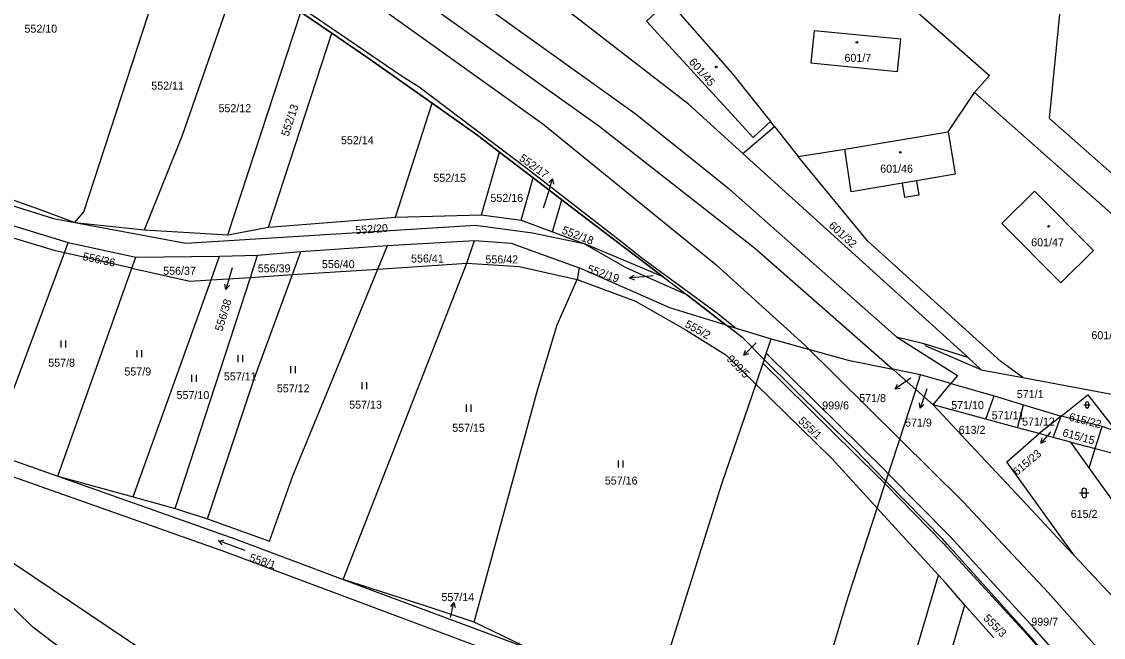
# Model space of a CAD drawing. Extents: x -757266 to -753360, y -1162585 to -1157740.
# Drawn here: x -756391.6 to -756161.8, y -1161170.8 to -1161040 of the extents above; entities that cross this region are included whole.
import ezdxf

# ---------------------------------------------------------------- set-up
doc = ezdxf.new("R2010")
doc.units = 0
for name, color, linetype in [('Hranice parcel', 7, 'Continuous'), ('Parcelní čísla', 7, 'Continuous'), ('Pop  PČ popisy', 7, 'Continuous'), ('Poz předměty', 7, 'Continuous'), ('Vnitřní kresba', 7, 'Continuous'), ('Věcná břemena k části', 7, 'Continuous'), ('Značky budov', 7, 'Continuous'), ('Značky kultur', 7, 'Continuous')]:
    doc.layers.add(name, color=color, linetype=linetype)

msp = doc.modelspace()

# ---------------------------------------------------------------- linework, layer by layer
at = {"layer": 'Hranice parcel'}
for p, q in [((-756347.81, -1161085.34), (-756332.31, -1161038.03)), ((-756325.74, -1161042.49), (-756332.31, -1161038.03)), ((-756339.16, -1161083.67), (-756325.74, -1161042.49)), ((-756194.79, -1161063.47), (-756189.22, -1161055.1)), ((-756189.22, -1161055.1), (-756130.57, -1161106.95)), ((-756312.16, -1161081.58), (-756304.38, -1161057.38)), ((-756238.39, -1161068.03), (-756231.69, -1161062.33)), ((-756231.69, -1161062.33), (-756232.53, -1161061.27)), ((-756231.69, -1161062.33), (-756226.63, -1161068.72)), ((-756216.76, -1161067.14), (-756194.79, -1161063.47)), ((-756226.63, -1161068.72), (-756216.76, -1161067.14)), ((-756293.95, -1161081.1), (-756290.12, -1161067.73)), ((-756282.98, -1161073.2), (-756290.12, -1161067.73)), ((-756190.6, -1161111.29), (-756238.39, -1161068.03)), ((-756285.46, -1161082.24), (-756282.98, -1161073.2)), ((-756276.88, -1161077.87), (-756282.98, -1161073.2)), ((-756278.82, -1161084.68), (-756276.88, -1161077.87)), ((-756402.04, -1161080.71), (-756381.71, -1161086.97)), ((-756312.16, -1161081.58), (-756293.95, -1161081.1)), ((-756293.95, -1161081.1), (-756285.46, -1161082.24)), ((-756380.33, -1161082.7), (-756365.53, -1161084.29)), ((-756347.81, -1161085.34), (-756339.16, -1161083.67)), ((-756339.16, -1161083.67), (-756312.16, -1161081.58)), ((-756285.46, -1161082.24), (-756278.82, -1161084.68)), ((-756365.53, -1161084.29), (-756347.81, -1161085.34)), ((-756278.82, -1161084.68), (-756272.16, -1161087.13)), ((-756382.52, -1161089.15), (-756381.71, -1161086.97)), ((-756381.71, -1161086.97), (-756367.38, -1161090.04)), ((-756332.27, -1161088.89), (-756313.86, -1161087.61)), ((-756315.91, -1161092.58), (-756313.86, -1161087.61)), ((-756313.86, -1161087.61), (-756295.39, -1161086.52)), ((-756297.07, -1161091.35), (-756295.39, -1161086.52)), ((-756255.3, -1161094.26), (-756272.16, -1161087.13)), ((-756398.32, -1161131.47), (-756382.52, -1161089.15)), ((-756368.21, -1161092.38), (-756382.52, -1161089.15)), ((-756368.21, -1161092.38), (-756367.38, -1161090.04)), ((-756367.38, -1161090.04), (-756349.55, -1161089.83)), ((-756351.37, -1161094.89), (-756349.55, -1161089.83)), ((-756349.55, -1161089.83), (-756341.48, -1161089.62)), ((-756343.02, -1161094.35), (-756341.48, -1161089.62)), ((-756341.48, -1161089.62), (-756332.27, -1161088.89)), ((-756334.06, -1161093.76), (-756332.27, -1161088.89)), ((-756383.91, -1161136.58), (-756368.21, -1161092.38)), ((-756334.06, -1161093.76), (-756315.91, -1161092.58)), ((-756323.3, -1161158.51), (-756297.07, -1161091.35)), ((-756315.91, -1161092.58), (-756297.07, -1161091.35)), ((-756273.15, -1161092.35), (-756273.61, -1161094.81)), ((-756367.91, -1161140.96), (-756351.37, -1161094.89)), ((-756359.01, -1161143.46), (-756343.02, -1161094.35)), ((-756351.37, -1161094.89), (-756343.02, -1161094.35)), ((-756343.02, -1161094.35), (-756334.06, -1161093.76)), ((-756255.3, -1161094.26), (-756250.36, -1161098)), ((-756241.96, -1161104.51), (-756250.36, -1161098)), ((-756241.96, -1161104.51), (-756232.4, -1161107.44)), ((-756233.87, -1161111.77), (-756232.4, -1161107.44)), ((-756233.87, -1161111.77), (-756235.67, -1161117.05)), ((-756206.58, -1161113.87), (-756201.69, -1161118.16)), ((-756200.68, -1161115.05), (-756206.58, -1161113.87)), ((-756201.69, -1161118.16), (-756200.68, -1161115.05)), ((-756194.25, -1161116.88), (-756200.68, -1161115.05)), ((-756201.69, -1161118.16), (-756208.01, -1161137.65)), ((-756197.99, -1161121.41), (-756201.69, -1161118.16)), ((-756197.99, -1161121.41), (-756194.25, -1161116.88)), ((-756194.25, -1161116.88), (-756185.01, -1161119.51)), ((-756186.8, -1161124.46), (-756185.01, -1161119.51)), ((-756185.01, -1161119.51), (-756178.8, -1161121.43)), ((-756186.8, -1161124.46), (-756197.99, -1161121.41)), ((-756180.08, -1161126.29), (-756178.8, -1161121.43)), ((-756178.8, -1161121.43), (-756170.8, -1161123.82)), ((-756180.08, -1161126.29), (-756186.8, -1161124.46)), ((-756170.8, -1161123.82), (-756175.48, -1161127.54)), ((-756172.5, -1161128.35), (-756170.8, -1161123.82)), ((-756162.05, -1161126.01), (-756170.8, -1161123.82)), ((-756175.48, -1161127.54), (-756180.08, -1161126.29)), ((-756159.03, -1161127.11), (-756162.05, -1161126.01)), ((-756172.5, -1161128.35), (-756175.48, -1161127.54)), ((-756398.32, -1161131.47), (-756383.91, -1161136.58)), ((-756153.73, -1161150.3), (-756164.84, -1161134.81)), ((-756383.91, -1161136.58), (-756367.91, -1161140.96)), ((-756209.87, -1161143.4), (-756208.01, -1161137.65)), ((-756367.91, -1161140.96), (-756359.01, -1161143.46)), ((-756209.87, -1161143.4), (-756196.87, -1161157.63)), ((-756359.01, -1161143.46), (-756352.09, -1161145.66)), ((-756167.94, -1161153.53), (-756157.64, -1161164.54)), ((-756323.3, -1161158.51), (-756283.74, -1161173.27)), ((-756185.1, -1161170.94), (-756191.26, -1161163.95)), ((-756283.74, -1161173.27), (-756295.45, -1161167.59))]:
    msp.add_line(p, q, dxfattribs=at)
for points in [[(-756619.33, -1160903.88), (-756577.49, -1160910.26), (-756516.69, -1160926.33), (-756477.86, -1160938.97), (-756467.28, -1160942.69), (-756436.37, -1160956.11), (-756402.66, -1160971.04), (-756365.31, -1160990.59), (-756332.18, -1161010.49), (-756327.59, -1161013.25), (-756311.79, -1161023.35), (-756261.25, -1161059.52), (-756244.95, -1161072.68), (-756241.63, -1161075.37), (-756205.74, -1161107.01)], [(-756619.9, -1160909.59), (-756570.69, -1160918.36), (-756518.23, -1160931.61), (-756479.8, -1160944.32), (-756438.52, -1160960.99), (-756404.97, -1160975.81), (-756367.56, -1160995.11), (-756330.79, -1161017.74), (-756301.4, -1161039.07), (-756269.03, -1161062.15), (-756235.9, -1161088.11), (-756216.97, -1161104.74), (-756206.58, -1161113.87)], [(-756108.4, -1161121.99), (-756143.44, -1161091.07), (-756148.04, -1161082.81), (-756173.25, -1161060.58), (-756158.32, -1160909.77)], [(-756284.06, -1160946.51), (-756265.23, -1160959.87), (-756261.78, -1160964.32), (-756259.59, -1160972.58), (-756254.14, -1160987.97), (-756251.24, -1160993.15), (-756247.24, -1160997.7), (-756201.76, -1161037.66), (-756186.03, -1161051.48), (-756189.22, -1161055.1)], [(-756238.39, -1161068.03), (-756249.95, -1161057.57), (-756286.42, -1161029.31), (-756325.51, -1161006.88), (-756320.49, -1160993.89), (-756312.28, -1160987.12), (-756309.4, -1160983.82)], [(-756380.33, -1161082.7), (-756378.4, -1161080.44), (-756358.96, -1161020.98)], [(-756365.53, -1161084.29), (-756357.4, -1161064.17), (-756345.3, -1161029.34)], [(-756232.53, -1161061.27), (-756236.18, -1161064.68), (-756258.84, -1161039.93), (-756254.18, -1161035.65)], [(-756254.18, -1161035.65), (-756240.57, -1161051.12), (-756232.53, -1161061.27)], [(-756204.82, -1161043.76), (-756223.27, -1161041.98), (-756223.94, -1161048.76), (-756205.52, -1161050.62), (-756204.82, -1161043.76)], [(-756304.38, -1161057.38), (-756318.26, -1161047.57), (-756325.74, -1161042.49)], [(-756503.07, -1161050.14), (-756482.76, -1161051.05), (-756384.84, -1161081.86), (-756380.33, -1161082.7)], [(-756290.12, -1161067.73), (-756294.69, -1161064.23), (-756304.38, -1161057.38)], [(-756194.79, -1161063.47), (-756193.29, -1161072.46), (-756201.55, -1161073.85), (-756201.05, -1161076.93), (-756203.99, -1161077.39), (-756204.5, -1161074.36), (-756215.42, -1161076.19), (-756216.76, -1161067.14)], [(-756417.55, -1161069.42), (-756387.87, -1161079.86), (-756380.33, -1161082.7)], [(-756178.9, -1161115.62), (-756183.59, -1161112.25), (-756211.93, -1161086.58), (-756226.63, -1161068.72)], [(-756170.89, -1161095.55), (-756183.39, -1161082.92), (-756176.42, -1161076.03), (-756163.94, -1161088.68), (-756170.89, -1161095.55)], [(-756255.3, -1161094.26), (-756269.72, -1161083.35), (-756276.88, -1161077.87)], [(-756382.52, -1161089.15), (-756384.41, -1161088.72), (-756403, -1161083.12)], [(-756380.33, -1161082.7), (-756356.72, -1161087.11), (-756295.17, -1161083.25), (-756283.1, -1161084.88), (-756272.16, -1161087.13)], [(-756295.39, -1161086.52), (-756287.63, -1161087.12), (-756273.15, -1161092.35)], [(-756272.16, -1161087.13), (-756263.25, -1161092.24), (-756250.36, -1161098)], [(-756368.21, -1161092.38), (-756355.85, -1161095.18), (-756351.37, -1161094.89)], [(-756352.09, -1161145.66), (-756338.96, -1161150.42), (-756334.03, -1161136.54), (-756315.91, -1161092.58)], [(-756297.07, -1161091.35), (-756285.9, -1161092.02), (-756273.61, -1161094.81)], [(-756241.96, -1161104.51), (-756253.93, -1161100.85), (-756273.15, -1161092.35)], [(-756352.09, -1161145.66), (-756342.18, -1161115.92), (-756334.06, -1161093.76)], [(-756295.45, -1161167.59), (-756282.01, -1161118.28), (-756277.83, -1161104.44), (-756273.61, -1161094.81)], [(-756273.61, -1161094.81), (-756261.22, -1161099.39), (-756250.3, -1161105.63), (-756242.04, -1161110.83), (-756235.67, -1161117.05)], [(-756233.87, -1161111.77), (-756238.37, -1161107.3), (-756241.96, -1161104.51)], [(-756232.4, -1161107.44), (-756216.05, -1161111.97), (-756206.58, -1161113.87)], [(-756205.74, -1161107.01), (-756199.98, -1161108.4), (-756190.6, -1161111.29)], [(-756205.74, -1161107.01), (-756192.84, -1161115.17), (-756194.25, -1161116.88)], [(-756208.01, -1161137.65), (-756214.86, -1161130.65), (-756233.87, -1161111.77)], [(-756190.6, -1161111.29), (-756187.81, -1161113.97), (-756178.9, -1161115.62)], [(-756178.9, -1161115.62), (-756140.04, -1161122.9), (-756113.43, -1161127.66)], [(-756235.67, -1161117.05), (-756242.91, -1161138.3), (-756255.92, -1161179.51), (-756258.81, -1161182.58)], [(-756235.67, -1161117.05), (-756219.53, -1161132.83), (-756209.87, -1161143.4)], [(-756170.8, -1161123.82), (-756165.1, -1161119.29), (-756159.03, -1161127.11)], [(-756289.81, -1161247.85), (-756323.85, -1161218.81), (-756352.34, -1161196.76), (-756389.25, -1161168.62), (-756413.98, -1161144.42), (-756440.09, -1161120.71)], [(-756437.21, -1161121.24), (-756348.29, -1161152.64), (-756260.39, -1161185.58)], [(-756277.8, -1161225.59), (-756364.81, -1161174.31), (-756397.31, -1161152.49), (-756437.21, -1161121.24)], [(-756197.99, -1161121.41), (-756188.99, -1161131.03), (-756183.37, -1161137.03), (-756177.1, -1161143.73), (-756169.72, -1161151.63), (-756167.94, -1161153.53)], [(-756164.84, -1161134.81), (-756163.54, -1161130.72), (-756162.05, -1161126.01)], [(-756167.94, -1161153.53), (-756182.35, -1161133.54), (-756175.48, -1161127.54)], [(-756164.84, -1161134.81), (-756168.73, -1161129.38), (-756172.5, -1161128.35)], [(-756383.91, -1161136.58), (-756346.14, -1161149.99), (-756323.3, -1161158.51)], [(-756157.07, -1161193.58), (-756163.59, -1161186.21), (-756175.51, -1161172.74), (-756177.18, -1161170.86), (-756183.13, -1161164.23), (-756189.32, -1161157.34), (-756194.93, -1161151.09), (-756195.96, -1161149.95), (-756208.01, -1161137.65)], [(-756248.25, -1161269.62), (-756215.93, -1161162.08), (-756209.87, -1161143.4)], [(-756295.45, -1161167.59), (-756305.43, -1161164.28), (-756323.3, -1161158.51)], [(-756231.49, -1161276.35), (-756202.05, -1161175.12), (-756196.87, -1161157.63)], [(-756191.26, -1161163.95), (-756195.25, -1161159.41), (-756196.87, -1161157.63)], [(-756224.06, -1161280.46), (-756199.31, -1161191.43), (-756191.26, -1161163.95)]]:
    msp.add_lwpolyline(points, dxfattribs=at)
at = {"layer": 'Pop  PČ popisy'}
for p, q in [((-756279.72, -1161076.3), (-756278.843, -1161073.43)), ((-756278.843, -1161073.43), (-756279.614, -1161074.241)), ((-756278.843, -1161073.43), (-756278.657, -1161074.534)), ((-756280.73, -1161079.56), (-756279.72, -1161076.3)), ((-756346.91, -1161092.33), (-756347.41, -1161094.04)), ((-756347.41, -1161094.04), (-756348.237, -1161096.925)), ((-756262.45, -1161094.472), (-756261.496, -1161093.885)), ((-756259.46, -1161094.21), (-756262.45, -1161094.472)), ((-756262.45, -1161094.472), (-756261.408, -1161094.883)), ((-756257.45, -1161094.02), (-756259.46, -1161094.21)), ((-756348.237, -1161096.925), (-756348.442, -1161095.824)), ((-756348.237, -1161096.925), (-756347.48, -1161096.1)), ((-756236.06, -1161108.76), (-756238.182, -1161110.882)), ((-756235.56, -1161108.26), (-756236.06, -1161108.76)), ((-756238.182, -1161110.882), (-756237.828, -1161109.82)), ((-756238.182, -1161110.882), (-756237.12, -1161110.528)), ((-756202.7, -1161115.74), (-756203.59, -1161116.34)), ((-756203.59, -1161116.34), (-756206.078, -1161118.018)), ((-756206.078, -1161118.018), (-756205.528, -1161117.043)), ((-756206.078, -1161118.018), (-756204.968, -1161117.873)), ((-756199.35, -1161118.06), (-756199.76, -1161119.28)), ((-756199.76, -1161119.28), (-756200.737, -1161122.117)), ((-756200.737, -1161122.117), (-756200.884, -1161121.008)), ((-756200.737, -1161122.117), (-756199.938, -1161121.334)), ((-756173.13, -1161127.29), (-756175.099, -1161129.555)), ((-756173.03, -1161127.18), (-756173.13, -1161127.29)), ((-756175.099, -1161129.555), (-756174.82, -1161128.471)), ((-756175.099, -1161129.555), (-756174.064, -1161129.128)), ((-756299.775, -1161163.416), (-756300.488, -1161164.279)), ((-756300.45, -1161166.34), (-756299.775, -1161163.416)), ((-756299.775, -1161163.416), (-756299.512, -1161164.504)), ((-756300.5, -1161166.58), (-756300.45, -1161166.34))]:
    msp.add_line(p, q, dxfattribs=at)
at = {"layer": 'Poz předměty'}
for p, q in [((-756318.84, -1161034.56), (-756280.92, -1161061.74)), ((-756280.92, -1161061.74), (-756244.17, -1161091.62)), ((-756244.17, -1161091.62), (-756225.27, -1161108.74)), ((-756225.27, -1161108.74), (-756191.67, -1161141.97)), ((-756191.67, -1161141.97), (-756173.56, -1161161.31)), ((-756173.56, -1161161.31), (-756155.48, -1161181.52))]:
    msp.add_line(p, q, dxfattribs=at)
at = {"layer": 'Vnitřní kresba'}
for p, q in [((-756201.55, -1161073.85), (-756204.5, -1161074.36)), ((-756199.98, -1161108.4), (-756199.34, -1161109.03)), ((-756187.81, -1161113.97), (-756199.34, -1161109.03)), ((-756168.73, -1161129.38), (-756163.54, -1161130.72)), ((-756163.54, -1161130.72), (-756154.4, -1161133.07))]:
    msp.add_line(p, q, dxfattribs=at)
at = {"layer": 'Věcná břemena k části'}
for points in [[(-756332.31, -1161038.03), (-756325.74, -1161042.49), (-756318.26, -1161047.57), (-756304.38, -1161057.38), (-756294.69, -1161064.23), (-756290.12, -1161067.73), (-756282.98, -1161073.2), (-756276.88, -1161077.87), (-756269.72, -1161083.35), (-756255.3, -1161094.26), (-756250.36, -1161098), (-756241.96, -1161104.51), (-756240.03, -1161105.1), (-756243.69, -1161102.08), (-756259.84, -1161090.3), (-756260.26, -1161089.95), (-756264.06, -1161086.97), (-756283.95, -1161071.51), (-756307.16, -1161053.98), (-756310.78, -1161051.69), (-756335.39, -1161034.83)], [(-756149.8, -1161200.9), (-756162.23, -1161185.13), (-756176.59, -1161168.81), (-756194.29, -1161149.48), (-756207.51, -1161136.1), (-756208.28, -1161135.32), (-756233, -1161110.9), (-756233.45, -1161110.53), (-756233.87, -1161111.77), (-756234.15, -1161112.58), (-756209.69, -1161136.73), (-756208.2, -1161138.24), (-756195.75, -1161150.85), (-756178.05, -1161170.17), (-756163.77, -1161186.41), (-756157.34, -1161194.55)]]:
    msp.add_lwpolyline(points, dxfattribs=at)
at = {"layer": 'Značky budov'}
for centre in [(-756214.1768, -1161044.4492), (-756244.0768, -1161049.6892), (-756204.9568, -1161067.7992), (-756173.4468, -1161083.5292)]:
    msp.add_circle(centre, 0.175, dxfattribs=at)
at = {"layer": 'Značky kultur'}
for p, q in [((-756383.231, -1161109.24), (-756383.231, -1161107.74)), ((-756382.23, -1161109.24), (-756382.23, -1161107.74)), ((-756367.061, -1161111.32), (-756367.061, -1161109.82)), ((-756366.06, -1161111.32), (-756366.06, -1161109.82)), ((-756345.611, -1161112.37), (-756345.611, -1161110.87)), ((-756344.61, -1161112.37), (-756344.61, -1161110.87)), ((-756334.451, -1161114.72), (-756334.451, -1161113.22)), ((-756333.45, -1161114.72), (-756333.45, -1161113.22)), ((-756355.451, -1161116.54), (-756355.451, -1161115.04)), ((-756354.45, -1161116.54), (-756354.45, -1161115.04)), ((-756319.251, -1161118.1), (-756319.251, -1161116.6)), ((-756318.25, -1161118.1), (-756318.25, -1161116.6)), ((-756297.111, -1161122.89), (-756297.111, -1161121.39)), ((-756296.11, -1161122.89), (-756296.11, -1161121.39)), ((-756165.951, -1161121.451), (-756164.609, -1161121.451)), ((-756165.615, -1161121.115), (-756165.615, -1161121.786)), ((-756164.945, -1161121.786), (-756164.945, -1161121.115)), ((-756264.821, -1161134.72), (-756264.821, -1161133.22)), ((-756263.82, -1161134.72), (-756263.82, -1161133.22)), ((-756166.891, -1161140.131), (-756164.889, -1161140.131)), ((-756166.391, -1161139.631), (-756166.391, -1161140.632)), ((-756165.389, -1161140.632), (-756165.389, -1161139.631)), ((-756349.762, -1161150.34), (-756348.673, -1161150.203)), ((-756344.124, -1161152.392), (-756349.762, -1161150.34)), ((-756349.762, -1161150.34), (-756349.016, -1161151.145))]:
    msp.add_line(p, q, dxfattribs=at)
for centre, radius, start, end in [((-756165.28, -1161121.1156), 0.335, 0, 180), ((-756165.28, -1161121.7856), 0.335, 180, 359.987886), ((-756165.89, -1161139.6309), 0.5, 0, 180), ((-756165.89, -1161140.6309), 0.5, 180, 359.987886)]:
    msp.add_arc(centre, radius, start, end, dxfattribs=at)

# ---------------------------------------------------------------- texts
at = {"layer": 'Parcelní čísla'}
for s, p in [('552/10', (-756391.01, -1161042.39)), ('601/7', (-756216.82, -1161048.58)), ('552/11', (-756364.07, -1161054.49)), ('552/12', (-756349.79, -1161059.28)), ('552/14', (-756323.78, -1161066.07)), ('601/46', (-756209.227, -1161072.11)), ('552/15', (-756304.16, -1161074.06)), ('552/16', (-756292.03, -1161078.33)), ('601/47', (-756177.157, -1161087.76)), ('556/41', (-756308.89, -1161091.2)), ('556/42', (-756293.09, -1161091.39)), ('556/37', (-756361.54, -1161093.81)), ('556/39', (-756341.45, -1161093.29)), ('556/40', (-756327.82, -1161092.39)), ('601/33', (-756164.37, -1161107.49)), ('557/8', (-756385.95, -1161113.32)), ('557/9', (-756369.78, -1161115.2)), ('557/11', (-756348.65, -1161116.24)), ('557/12', (-756337.4, -1161118.77)), ('557/10', (-756358.7, -1161120.21)), ('557/13', (-756322.03, -1161122.24)), ('571/8', (-756213.687, -1161120.848)), ('571/1', (-756180.22, -1161120.01)), ('999/6', (-756221.55, -1161122.4)), ('571/10', (-756194.15, -1161122.34)), ('571/11', (-756185.54, -1161124.5)), ('571/9', (-756203.947, -1161126.048)), ('571/12', (-756179.09, -1161125.84)), ('557/15', (-756300.15, -1161127.16)), ('613/2', (-756192.56, -1161127.59)), ('557/16', (-756267.73, -1161138.36)), ('615/2', (-756168.76, -1161145.44)), ('557/14', (-756302.43, -1161163.12)), ('999/7', (-756177.13, -1161168.34))]:
    msp.add_text(s, height=1.7, dxfattribs=at).set_placement(p)
for s, rotation, p in [('601/45', 311, (-756249.981, -1161048.688)), ('552/13', 72, (-756334.911, -1161064.532)), ('552/17', 324, (-756286.077, -1161069.386)), ('552/20', 4, (-756320.68, -1161085.177)), ('552/18', 339, (-756276.994, -1161084.973)), ('601/32', 318, (-756220.308, -1161083.581)), ('556/36', 348, (-756378.726, -1161090.661)), ('552/19', 340.999997, (-756271.601, -1161093.243)), ('556/38', 73, (-756348.994, -1161105.933)), ('555/2', 331, (-756250.862, -1161104.803)), ('999/5', 313.999997, (-756241.961, -1161111.833)), ('555/1', 317, (-756226.769, -1161125.021)), ('615/22', 346, (-756169.255, -1161124.744)), ('615/15', 345, (-756170.639, -1161128.061)), ('615/23', 40, (-756180.166, -1161136.547)), ('558/1', 342, (-756343.372, -1161154.578)), ('555/3', 315, (-756187.441, -1161166.911))]:
    msp.add_text(s, height=1.7, rotation=rotation, dxfattribs=at).set_placement(p)

doc.saveas('drawing.dxf')
